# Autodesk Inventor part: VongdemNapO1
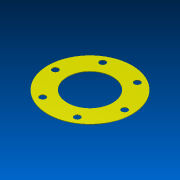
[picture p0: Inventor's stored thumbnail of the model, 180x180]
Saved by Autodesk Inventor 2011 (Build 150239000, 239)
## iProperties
Created: 2011-05
Part Number: VongdemNapO1
Document SubType Name: Modeling
Designer: 904Chiaki
Density: 1 g/cm^3
Mass: 11.6066 g
Surface Area: 241.369 cm^2
Volume: 11.6066 cm^3
Author: 904Chiaki
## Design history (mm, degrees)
sketch "Sketch1"
  geometry: C1 r 40 at (-61.197, 10.417); C2 r 74 at (-61.197, 10.417); 1 further point
  constraints: 2 centre point, 1 coincident
  dimensions: "d0" = 80 diameter of C1; "d1" = 148 diameter of C2
extrude "Extrusion1" new body sketch "Sketch1" distance "d2" = 1; taper "d3" = 0 deg
workplane "Work Plane1"
  workaxis "Work Axis1"
node "Hole2"
body "Solid1"
sketch "Sketch2"
  geometry: 6 further points
hole "Hole1" sketch "Sketch2" diameter "d5" = 11; stored, may be unused: countersink angle "d9" = 90 deg, drill point angle "d11" = 0 deg; dims "d6" = 6, "d7" = 4, "d8" = 2, "d10" = 8
other parameters: "d4" = 90 deg
